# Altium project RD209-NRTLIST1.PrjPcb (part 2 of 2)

## Sheet 4.SchDoc
size 420 x 297 mm
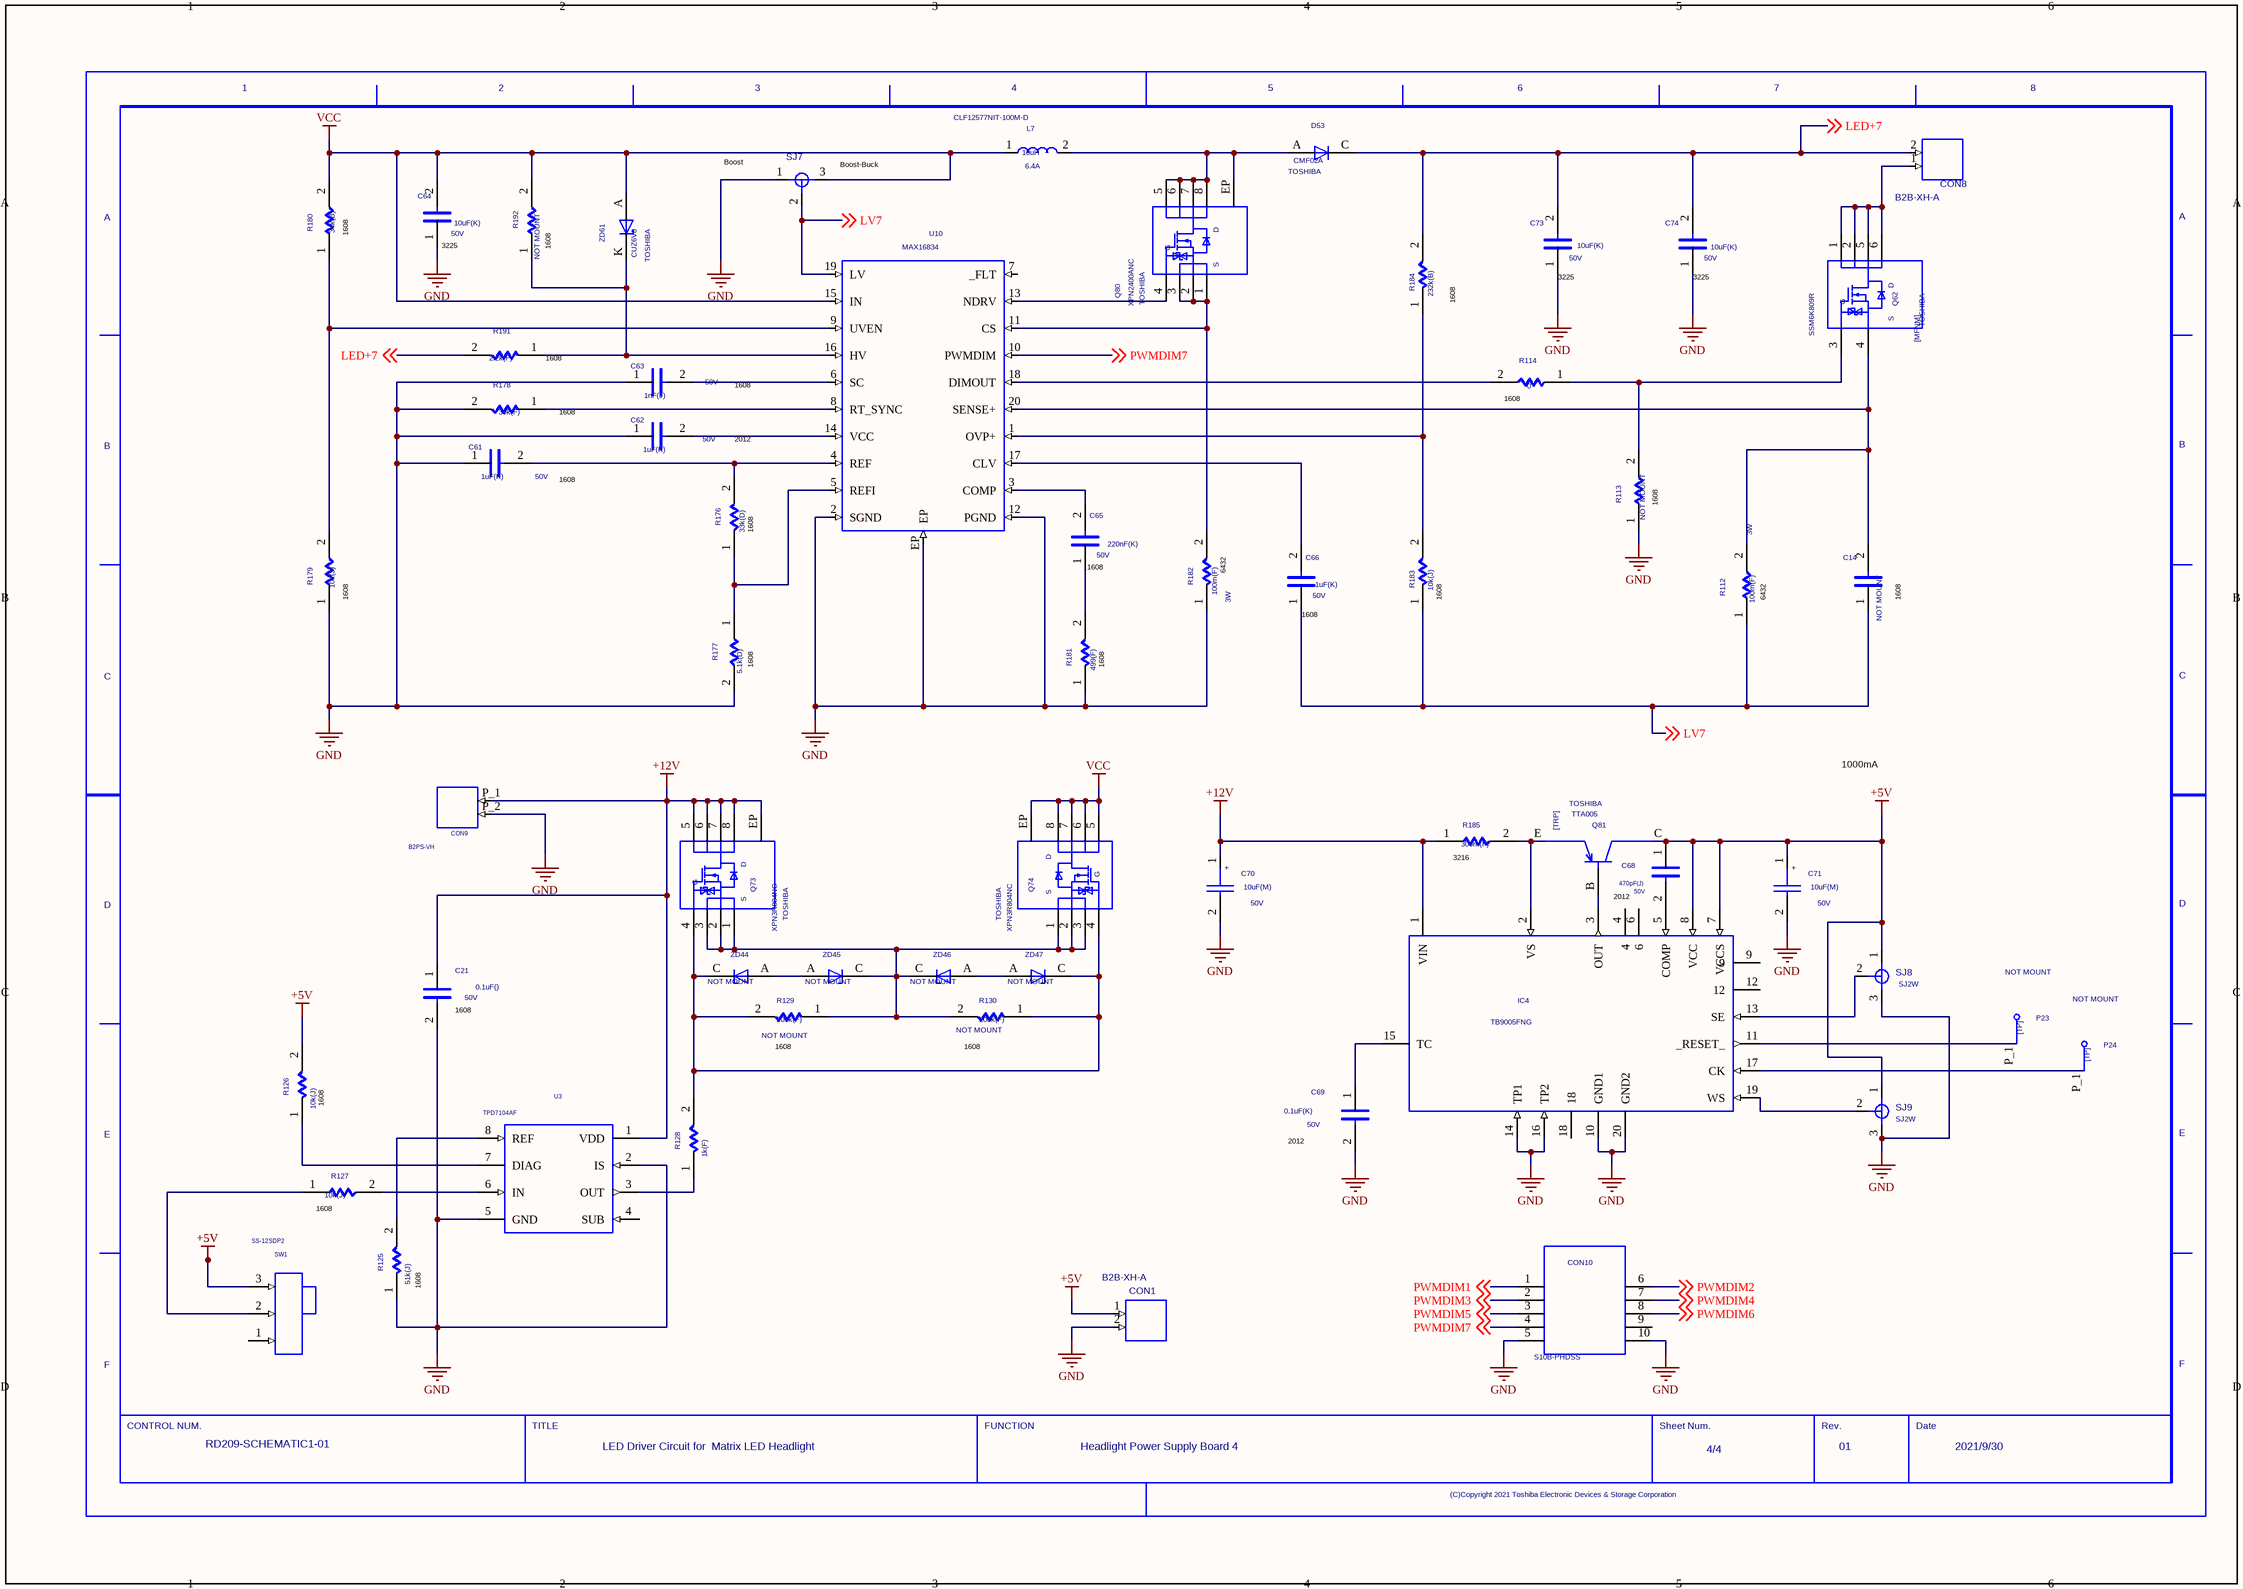
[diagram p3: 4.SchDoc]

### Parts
(Parts that share a designator on the sheet are numbered #1, #2 ... from top to bottom, then left to right.)
C14  NOTMOUNT: NOT MOUNT  (hidden comment: C)
C21  VAL2: 50V  VAL1: 0.1uF()  (hidden comment: C)
C61  VAL2: 50V  VAL1: 1uF(K)  (hidden comment: C)
C62  VAL2: 50V  VAL1: 1uF(K)  (hidden comment: C)
C63  VAL2: 50V  VAL1: 1nF(J)  (hidden comment: C)
C64  VAL2: 50V  VAL1: 10uF(K)  (hidden comment: C)
C65  VAL2: 50V  VAL1: 220nF(K)  (hidden comment: C)
C66  VAL2: 50V  VAL1: 1uF(K)  (hidden comment: C)
C68  VAL2: 50V  VAL1: 470pF(J)  (hidden comment: C)
C69  VAL2: 50V  VAL1: 0.1uF(K)  (hidden comment: C)
C70  VAL2: 50V  VAL1: 10uF(M)  (hidden comment: CP)
C71  VAL2: 50V  VAL1: 10uF(M)  (hidden comment: CP)
C73  VAL2: 50V  VAL1: 10uF(K)  (hidden comment: C)
C74  VAL2: 50V  VAL1: 10uF(K)  (hidden comment: C)
CON1  B2B-XH-A  [B2B-XH-A]
CON8  B2B-XH-A  [B2B-XH-A]
CON9  B2PS-VH  [B2PS-VH]
CON10  VAL3: S10B-PHDSS  (hidden comment: CON10_5X5)
D53  USERCOMPTEXT3: TOSHIBA  VAL3: CMF02A  (hidden comment: D)
IC4  TB9005FNG
L7  VAL3: CLF12577NIT-100M-D  VAL2: 6.4A  VAL1: 10uH  (hidden comment: L)
P23  NOTMOUNT: NOT MOUNT  (hidden comment: TP)
P24  NOTMOUNT: NOT MOUNT  (hidden comment: TP)
Q62  USERCOMPTEXT3: TOSHIBA  VAL3: SSM6K809R  (hidden comment: MFNM)
Q73  USERCOMPTEXT3: TOSHIBA  VAL3: XPN3R804NC  (hidden comment: MFNKR1)
Q74  USERCOMPTEXT3: TOSHIBA  VAL3: XPN3R804NC  (hidden comment: MFNKR1)
Q80  USERCOMPTEXT3: TOSHIBA  VAL3: XPN2400ANC  (hidden comment: MFNKR1)
Q81  USERCOMPTEXT3: TOSHIBA  VAL3: TTA005  (hidden comment: TRP)
R112  VAL2: 3W  VAL1: 100m(F)  (hidden comment: R)
R113  NOTMOUNT: NOT MOUNT  (hidden comment: R)
R114  VAL1: 0  (hidden comment: R)
R125  VAL1: 51k(J)  (hidden comment: R)
R126  VAL1: 10k(J)  (hidden comment: R)
R127  VAL1: 10k(J)  (hidden comment: R)
R128  VAL1: 1k(F)  (hidden comment: R)
R129  NOTMOUNT: NOT MOUNT  VAL1: 200k(F)  (hidden comment: R)
R130  NOTMOUNT: NOT MOUNT  VAL1: 200k(F)  (hidden comment: R)
R176  VAL1: 33k(D)  (hidden comment: R)
R177  VAL1: 5.1k(D)  (hidden comment: R)
R178  VAL1: 39k(F)  (hidden comment: R)
R179  VAL1: 10k(J)  (hidden comment: R)
R180  VAL1: 34k(B)  (hidden comment: R)
R181  VAL1: 499(F)  (hidden comment: R)
R182  VAL2: 3W  VAL1: 100m(F)  (hidden comment: R)
R183  VAL1: 10k(J)  (hidden comment: R)
R184  VAL1: 232k(B)  (hidden comment: R)
R185  VAL1: 300m(F)  (hidden comment: R)
R191  VAL1: 2.2k(F)  (hidden comment: R)
R192  NOTMOUNT: NOT MOUNT  (hidden comment: R)
SJ7  SJ2W  (value not drawn)
SJ8  SJ2W
SJ9  SJ2W
SW1  SS-12SDP2  [SS-12SDP2]
U3  TPD7104AF  [PS-8]
U10  MAX16834
U?#4  DATE: 2021/9/30  REVISION: 01  DRAWINGNUMBER: RD209-SCHEMATIC1-01  FUNCTION: Headlight Power Supply Board 4  SHEETNUMBER: 4/4  TITLE: LED Driver Circuit for / Matrix LED Headlight  (hidden comment: WAKU_DEF100)
ZD44  NOTMOUNT: NOT MOUNT  (hidden comment: ZD)
ZD45  NOTMOUNT: NOT MOUNT  (hidden comment: ZD)
ZD46  NOTMOUNT: NOT MOUNT  (hidden comment: ZD)
ZD47  NOTMOUNT: NOT MOUNT  (hidden comment: ZD)
ZD61  USERCOMPTEXT3: TOSHIBA  VAL3: CUZ6V8  (hidden comment: ZD)

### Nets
+5V: C68.1 C71.1 CON1.1 IC4.7(VCCS) IC4.8(VCC) Q81.C R126.2 SJ8.1 SJ9.1 SW1.3
+12V: C21.1 C70.1 CON9.P_1 IC4.1(VIN) Q73.5 Q73.6 Q73.7 Q73.8 Q73.EP R185.1 U3.1(VDD)
GND: C21.2 C61.1 C62.1 C63.1 C64.1 C69.2 C70.2 C71.2 C73.1 C74.1 CON1.2 CON9.P_2 CON10.5 CON10.10 IC4.10(GND1) IC4.14(TP1) IC4.16(TP2) IC4.20(GND2) R113.1 R125.1 R177.2 R178.2 R179.1 R181.1 R182.1 SJ7.1 SJ8.3 SJ9.3 U3.2(IS) U3.5(GND) U10.2(SGND) U10.12(PGND) U10.EP
VCC: C64.2 L7.1 Q74.5 Q74.6 Q74.7 Q74.8 Q74.EP R180.2 R192.2 SJ7.3 U10.15(IN) ZD61.A
LED+7: C73.2 C74.2 CON8.2 D53.C R184.2 R191.2 ; off-sheet LED+7
LV7: C14.1 C66.1 R112.1 R183.1 SJ7.2 U10.19(LV) ; off-sheet LV7
PWMDIM1: CON10.1 ; off-sheet PWMDIM1
PWMDIM2: CON10.6 ; off-sheet PWMDIM2
PWMDIM3: CON10.2 ; off-sheet PWMDIM3
PWMDIM4: CON10.7 ; off-sheet PWMDIM4
PWMDIM5: CON10.3 ; off-sheet PWMDIM5
PWMDIM6: CON10.8 ; off-sheet PWMDIM6
PWMDIM7: CON10.4 U10.10(PWMDIM) ; off-sheet PWMDIM7
SIG1: Q80.4 U10.13(NDRV)
SIG494: R127.2 U3.6(IN)
SIG518: C69.1 IC4.15(TC)
SIG595: IC4.13(SE) SJ8.2
SIG623: ZD46.A ZD47.A
SIG625: ZD44.A ZD45.A
SIG626: Q73.1 Q73.2 Q73.3 Q74.1 Q74.2 Q74.3 R129.1 R130.2 ZD45.C ZD46.C
SIG628: Q73.4 Q74.4 R128.2 R129.2 R130.1 ZD44.C ZD47.C
SIG631: R126.1 U3.7(DIAG)
SIG632: R125.2 U3.8(REF)
SIG634: R127.1 SW1.2
SIG635: R128.1 U3.3(OUT)
SIG638: IC4.3(OUT) Q81.B
SIG639: IC4.2(VS) Q81.E R185.2
SIG642: IC4.19(WS) SJ9.2
SIG643: IC4.17(CK) P24.P_1
SIG644: IC4.11(_RESET_) P23.P_1
SIG771: R178.1 U10.8(RT_SYNC)
SIG775: C62.2 U10.14(VCC)
SIG778: R176.1 R177.1 U10.5(REFI)
SIG779: C63.2 U10.6(SC)
SIG781: C65.2 U10.3(COMP)
SIG782: C66.2 U10.17(CLV)
SIG783: C61.2 R176.2 U10.4(REF)
SIG784: Q80.1 Q80.2 Q80.3 R182.2 U10.11(CS)
SIG785: R191.1 R192.1 U10.16(HV) ZD61.K(C)
SIG787: CON8.1 Q62.1 Q62.2 Q62.5 Q62.6
SIG788: Q62.3 R113.2 R114.1
SIG789: C65.1 R181.2
SIG791: C14.2 Q62.4 R112.2 U10.20(SENSE+)
SIG794: R114.2 U10.18(DIMOUT)
SIG795: R183.2 R184.1 U10.1(OVP+)
SIG796: R179.2 R180.1 U10.9(UVEN)
SIG800: D53.A L7.2 Q80.5 Q80.6 Q80.7 Q80.8 Q80.EP
NetC68_2: C68.2 IC4.5(COMP)

Not connected (* = marked no-connect by the designer): CON10 9; IC4 4 6 9 12 18; SW1 1; U3 4(SUB); U10 7(_FLT)

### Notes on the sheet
- (near SJ7) Boost
- (near SJ7) Boost-Buck
- (near R180) 1608
- (near C64) 3225
- (near R192) 1608
- (near R184) 1608
- (near C73) 3225
- (near C74) 3225
- (near R191) 1608
- 1608
- (near R178) 1608
- 2012
- (near R114) 1608
- (near R176) 1608
- (near R113) 1608
- (near R179) 1608
- (near C65) 1608
- (near R182) 6432
- (near R183) 1608
- (near R112) 6432
- (near C14) 1608
- (near R177) 1608
- (near R181) 1608
- (near C66) 1608
- 1000mA
- (near R185) 3216
- (near C21) 1608
- (near R129) 1608
- (near R130) 1608
- (near R126) 1608
- (near R127) 1608
- (near R125) 1608

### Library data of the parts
C14 = C: TIME: 17:22:43; UPDATEUSER: t5459927; SAVECOUNT: 1; OriginalSymbolOrigin: (2540,7620); INSTANCENAME: cmp227; CDBNAME: C0603K
C21 = C: TIME: 17:22:43; UPDATEUSER: t5459927; SAVECOUNT: 1; OriginalSymbolOrigin: (2540,7620); INSTANCENAME: cmp126; CDBNAME: C0603K_2
C61 = C: TIME: 17:22:43; UPDATEUSER: t5459927; SAVECOUNT: 1; OriginalSymbolOrigin: (2540,7620); INSTANCENAME: cmp225; CDBNAME: C0603K_3
C62 = C: TIME: 17:22:43; UPDATEUSER: t5459927; SAVECOUNT: 1; OriginalSymbolOrigin: (2540,7620); INSTANCENAME: cmp205; CDBNAME: C0805K_1
C63 = C: TIME: 17:22:43; UPDATEUSER: t5459927; SAVECOUNT: 1; OriginalSymbolOrigin: (2540,7620); INSTANCENAME: cmp236; CDBNAME: C0603K_1
C64 = C: TIME: 17:22:43; UPDATEUSER: t5459927; SAVECOUNT: 1; OriginalSymbolOrigin: (2540,7620); INSTANCENAME: cmp209; CDBNAME: C1210K
C65 = C: TIME: 17:22:43; UPDATEUSER: t5459927; SAVECOUNT: 1; OriginalSymbolOrigin: (2540,7620); INSTANCENAME: cmp219; CDBNAME: C0603K_4
C66 = C: TIME: 17:22:43; UPDATEUSER: t5459927; SAVECOUNT: 1; OriginalSymbolOrigin: (2540,7620); INSTANCENAME: cmp231; CDBNAME: C0603K_3
C68 = C: TIME: 17:22:43; UPDATEUSER: t5459927; SAVECOUNT: 1; OriginalSymbolOrigin: (2540,7620); INSTANCENAME: cmp141; CDBNAME: C0805K_2
C69 = C: TIME: 17:22:43; UPDATEUSER: t5459927; SAVECOUNT: 1; OriginalSymbolOrigin: (2540,7620); INSTANCENAME: cmp152; CDBNAME: C0805K_3
C70 = CP: TIME: 17:22:43; SAVECOUNT: 1; SAVEAREA0: -1450,-153,20294,13055; COMP: C; UPDATEUSER: t5459927; OriginalSymbolOrigin: (2540,10160); INSTANCENAME: cmp135; CDBNAME: UD-6_3X5_8_NICHICON
C71 = CP: TIME: 17:22:43; SAVECOUNT: 1; SAVEAREA0: -1450,-153,20294,13055; COMP: C; UPDATEUSER: t5459927; OriginalSymbolOrigin: (2540,10160); INSTANCENAME: cmp197; CDBNAME: UD-6_3X5_8_NICHICON
C73 = C: TIME: 17:22:43; UPDATEUSER: t5459927; SAVECOUNT: 1; OriginalSymbolOrigin: (2540,7620); INSTANCENAME: cmp220; CDBNAME: C1210K
C74 = C: TIME: 17:22:43; UPDATEUSER: t5459927; SAVECOUNT: 1; OriginalSymbolOrigin: (2540,7620); INSTANCENAME: cmp234; CDBNAME: C1210K
CON1 = B2B_XH_A: SAVECOUNT: 1; COMP: B2_BX_HA; UPDATEUSER: t5459927; UPDATETIME: 17:22:42; OriginalSymbolOrigin: (0,0); COMPONENTNAME: CON; INSTANCENAME: INS9244
CON8 = B2B_XH_A: SAVECOUNT: 1; COMP: B2_BX_HA; UPDATEUSER: t5459927; UPDATETIME: 17:22:42; OriginalSymbolOrigin: (0,0); COMPONENTNAME: CON; INSTANCENAME: INS9160
CON9 = B2PS_VH: SAVECOUNT: 1; UPDATEUSER: t5459927; UPDATETIME: 17:22:42; OriginalSymbolOrigin: (0,0); COMPONENTNAME: CON; INSTANCENAME: INS9280
CON10 = CON10_5X5: TIME: 17:22:42; SAVECOUNT: 1; SAVEAREA0: -6378,-413,31795,20718; COMP: CON10; UPDATEUSER: t5459927; OriginalSymbolOrigin: (5080,22860); COMPONENTNAME: CON; INSTANCENAME: cmp189; CDBNAME: GDM220002192
D53 = D: SAVEAREA0: -225,-91,12804,7836; SAVECOUNT: 3; TIME: 14:49:55; UPDATEUSER: 19870035; UPDATETIME: 14:20:16; OriginalSymbolOrigin: (5080,5080); CDBNAME: M-FLAT
IC4 = TB9005FNG: SAVECOUNT: 3; SAVEAREA0: -26622,-27385,86055,19754; UPDATEUSER: t5459927; UPDATETIME: 09:48:39; TIME: 17:22:42; OriginalSymbolOrigin: (0,0); COMPONENTNAME: IC
L7 = L: COMP: CLF12577NI_D; TIME: 17:22:43; UPDATEUSER: t5459927; SAVECOUNT: 1; OriginalSymbolOrigin: (2540,5080); INSTANCENAME: cmp206; CDBNAME: CLF12577NI-D
P23 = TP: TIME: 17:22:42; SAVECOUNT: 1; SAVEAREA0: -242,-92,12810,7836; COMP: HT; UPDATEUSER: t5459927; OriginalSymbolOrigin: (0,7620); INSTANCENAME: cmp147; CDBNAME: CT
P24 = TP: TIME: 17:22:42; SAVECOUNT: 1; SAVEAREA0: -242,-92,12810,7836; COMP: HT; UPDATEUSER: t5459927; OriginalSymbolOrigin: (0,7620); INSTANCENAME: cmp146; CDBNAME: CT
Q62 = MFNM: TIME: 17:22:43; SAVECOUNT: 1; SAVEAREA0: -6986,-322,29385,23602; UPDATEUSER: t5459927; OriginalSymbolOrigin: (5080,20320); COMPONENTNAME: Q; INSTANCENAME: cmp215; CDBNAME: TSOP6F
Q73 Q74 = MFNKR1: TIME: 17:22:43; SAVECOUNT: 2; SAVEAREA0: -5755,-491,27794,24105; COMP: TSON_ADVANCE_WF_2; UPDATETIME: 09:26:31; UPDATEUSER: t5459927; OriginalSymbolOrigin: (5080,20320); COMPONENTNAME: Q
Q80 = MFNKR1: TIME: 17:22:43; SAVECOUNT: 2; SAVEAREA0: -5755,-491,27794,24105; COMP: TSON_ADVANCE_WF_1; UPDATETIME: 09:26:31; UPDATEUSER: t5459927; OriginalSymbolOrigin: (5080,20320); COMPONENTNAME: Q
Q81 = TRP: TIME: 17:22:43; SAVECOUNT: 1; SAVEAREA0: -5466,-244,29263,20886; UPDATEUSER: t5459927; OriginalSymbolOrigin: (5080,22860); COMPONENTNAME: Q; INSTANCENAME: cmp138
R112 = R: TIME: 17:22:43; UPDATEUSER: t5459927; SAVECOUNT: 1; OriginalSymbolOrigin: (5080,5080); INSTANCENAME: cmp226; CDBNAME: R2512
R113 = R: TIME: 17:22:43; UPDATEUSER: t5459927; SAVECOUNT: 1; OriginalSymbolOrigin: (5080,5080); INSTANCENAME: cmp240; CDBNAME: R0603
R114 = R: TIME: 17:22:43; UPDATEUSER: t5459927; SAVECOUNT: 1; OriginalSymbolOrigin: (5080,5080); INSTANCENAME: cmp233; CDBNAME: R0603_7
R125 = R: TIME: 17:22:43; UPDATEUSER: t5459927; SAVECOUNT: 1; OriginalSymbolOrigin: (5080,5080); VAL2: 100mW; INSTANCENAME: cmp131; CDBNAME: R0603_3
R126 = R: TIME: 17:22:43; UPDATEUSER: t5459927; SAVECOUNT: 1; OriginalSymbolOrigin: (5080,5080); VAL2: 100mW; INSTANCENAME: cmp130; CDBNAME: R0603_6
R127 = R: TIME: 17:22:43; UPDATEUSER: t5459927; SAVECOUNT: 1; OriginalSymbolOrigin: (5080,5080); VAL2: 100mW; INSTANCENAME: cmp132; CDBNAME: R0603_6
R128 = R: TIME: 17:22:43; UPDATEUSER: t5459927; SAVECOUNT: 1; OriginalSymbolOrigin: (5080,5080); VAL2: 125mW; INSTANCENAME: cmp125; CDBNAME: R0603_4
R129 = R: TIME: 17:22:43; UPDATEUSER: t5459927; SAVECOUNT: 1; OriginalSymbolOrigin: (5080,5080); VAL2: 100mW; INSTANCENAME: cmp121; CDBNAME: R0603_5
R130 = R: TIME: 17:22:43; UPDATEUSER: t5459927; SAVECOUNT: 1; OriginalSymbolOrigin: (5080,5080); VAL2: 100mW; INSTANCENAME: cmp120; CDBNAME: R0603_5
R176 = R#1: TIME: 17:22:43; UPDATEUSER: t5459927; SAVECOUNT: 1; OriginalSymbolOrigin: (5080,5080); CaptureCellPackProp: R##1; VAL2: 100mW; INSTANCENAME: cmp214; CDBNAME: R0603_11
R177 = R: TIME: 17:22:43; UPDATEUSER: t5459927; SAVECOUNT: 1; OriginalSymbolOrigin: (5080,5080); VAL2: 100mW; INSTANCENAME: cmp208; CDBNAME: R0603_10
R178 = R: TIME: 17:22:43; UPDATEUSER: t5459927; SAVECOUNT: 1; OriginalSymbolOrigin: (5080,5080); VAL2: 100mW; INSTANCENAME: cmp224; CDBNAME: R0603_8
R179 = R: TIME: 17:22:43; UPDATEUSER: t5459927; SAVECOUNT: 1; OriginalSymbolOrigin: (5080,5080); VAL2: 100mW; INSTANCENAME: cmp228; CDBNAME: R0603_6
R180 = R: TIME: 17:22:43; UPDATEUSER: t5459927; SAVECOUNT: 1; OriginalSymbolOrigin: (5080,5080); VAL2: 100mW; INSTANCENAME: cmp238; CDBNAME: R0603_1
R181 = R: TIME: 17:22:43; UPDATEUSER: t5459927; SAVECOUNT: 1; OriginalSymbolOrigin: (5080,5080); VAL2: 125mW; INSTANCENAME: cmp239; CDBNAME: R0603_12
R182 = R: TIME: 17:22:43; UPDATEUSER: t5459927; SAVECOUNT: 1; OriginalSymbolOrigin: (5080,5080); INSTANCENAME: cmp223; CDBNAME: R2512
R183 = R: TIME: 17:22:43; UPDATEUSER: t5459927; SAVECOUNT: 1; OriginalSymbolOrigin: (5080,5080); VAL2: 100mW; INSTANCENAME: cmp242; CDBNAME: R0603_6
R184 = R: TIME: 17:22:43; UPDATEUSER: t5459927; SAVECOUNT: 1; OriginalSymbolOrigin: (5080,5080); VAL2: 63mW; INSTANCENAME: cmp229; CDBNAME: R0603_9
R185 = R: TIME: 17:22:43; UPDATEUSER: t5459927; SAVECOUNT: 1; OriginalSymbolOrigin: (5080,5080); VAL2: 1.5W; INSTANCENAME: cmp140; CDBNAME: R1206
R191 = R: TIME: 17:22:43; UPDATEUSER: t5459927; SAVECOUNT: 1; OriginalSymbolOrigin: (5080,5080); VAL2: 100mW; INSTANCENAME: cmp212; CDBNAME: R0603_2
R192 = R: TIME: 17:22:43; UPDATEUSER: t5459927; SAVECOUNT: 1; OriginalSymbolOrigin: (5080,5080); INSTANCENAME: cmp244; CDBNAME: R0603
SJ7 = SJ2W: SAVECOUNT: 1; COMP: SJ_2; SAVEAREA0: -15743,-4510,23437,11881; UPDATEUSER: t5459927; UPDATETIME: 17:22:42; OriginalSymbolOrigin: (2540,7620); COMPONENTNAME: SJ; INSTANCENAME: cmp237
SJ8 = SJ2W: SAVECOUNT: 1; COMP: SJ_2; SAVEAREA0: -15743,-4510,23437,11881; UPDATEUSER: t5459927; UPDATETIME: 17:22:42; OriginalSymbolOrigin: (2540,7620); COMPONENTNAME: SJ; INSTANCENAME: cmp143
SJ9 = SJ2W: SAVECOUNT: 1; COMP: SJ_2; SAVEAREA0: -15743,-4510,23437,11881; UPDATEUSER: t5459927; UPDATETIME: 17:22:42; OriginalSymbolOrigin: (2540,7620); COMPONENTNAME: SJ; INSTANCENAME: cmp144
SW1 = SS_12SDP2: SAVECOUNT: 1; UPDATEUSER: t5459927; UPDATETIME: 17:22:42; OriginalSymbolOrigin: (0,0); COMPONENTNAME: SW; INSTANCENAME: INS6128
U3 = TPD7104AF: SAVECOUNT: 1; UPDATEUSER: t5459927; UPDATETIME: 17:22:42; OriginalSymbolOrigin: (0,0); COMPONENTNAME: IC; INSTANCENAME: INS6060
U10 = MAX16834: SAVECOUNT: 1; COMP: 20-TQFN; SAVEAREA0: -47937,-54417,76568,2975; UPDATEUSER: t5459927; UPDATETIME: 17:22:42; OriginalSymbolOrigin: (0,0); COMPONENTNAME: IC; INSTANCENAME: cmp580
U?#4 = WAKU_DEF100: PLOTTIME: HH:MM; SAVEAREA0: 147884,-66467,487065,89883; TIME: 14:30:25; UPDATEUSER: t5459927; UPDATETIME: 12:50:54; SAVECOUNT: 7; OriginalSymbolOrigin: (10160,284480)
ZD44 = ZD#1: TIME: 17:22:43; SAVECOUNT: 1; SAVEAREA0: -4630,-153,17114,13055; UPDATEUSER: t5459927; OriginalSymbolOrigin: (5080,5080); CaptureCellPackProp: ZD##1; INSTANCENAME: cmp122; CDBNAME: ZD-16V
ZD45 = ZD#1: TIME: 17:22:43; SAVECOUNT: 1; SAVEAREA0: -4630,-153,17114,13055; UPDATEUSER: t5459927; OriginalSymbolOrigin: (5080,5080); CaptureCellPackProp: ZD##1; INSTANCENAME: cmp123; CDBNAME: ZD-16V
ZD46 = ZD#1: TIME: 17:22:43; SAVECOUNT: 1; SAVEAREA0: -4630,-153,17114,13055; UPDATEUSER: t5459927; OriginalSymbolOrigin: (5080,5080); CaptureCellPackProp: ZD##1; INSTANCENAME: cmp119; CDBNAME: ZD-16V
ZD47 = ZD#1: TIME: 17:22:43; SAVECOUNT: 1; SAVEAREA0: -4630,-153,17114,13055; UPDATEUSER: t5459927; OriginalSymbolOrigin: (5080,5080); CaptureCellPackProp: ZD##1; INSTANCENAME: cmp118; CDBNAME: ZD-16V
ZD61 = ZD: TIME: 17:22:43; SAVECOUNT: 1; SAVEAREA0: -4630,-153,17114,13055; UPDATEUSER: t5459927; OriginalSymbolOrigin: (5080,5080); INSTANCENAME: cmp201; CDBNAME: USC

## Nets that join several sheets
GND: 1 (32 pins), 2 (32 pins), 3 (32 pins), 4 (33 pins)
VCC: 1 (14 pins), 2 (14 pins), 3 (14 pins), 4 (12 pins)
PWMDIM1: 1 (U1.10), 4 (CON10.1)
PWMDIM2: 1 (U5.10), 4 (CON10.6)
PWMDIM3: 2 (U6.10), 4 (CON10.2)
PWMDIM4: 2 (U7.10), 4 (CON10.7)
PWMDIM5: 3 (U8.10), 4 (CON10.3)
PWMDIM6: 3 (U9.10), 4 (CON10.8)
